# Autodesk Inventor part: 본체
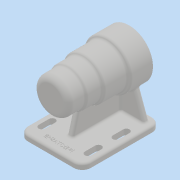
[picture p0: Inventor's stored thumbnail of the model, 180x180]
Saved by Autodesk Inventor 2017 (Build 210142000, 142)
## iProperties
Part Number: 본체
Material: 일반
Document SubType Name: Modeling
Designer: MRC
Density: 1 g/cm^3
Appearance: 기본값
Author: MRC
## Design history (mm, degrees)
sketch "스케치1"
  geometry: C1 r 34 at (0, 0); 1 further point
  constraints: 1 centre point, 1 coincident
  dimensions: "d0" = 68 diameter of C1
extrude "돌출1" new body sketch "스케치1" distance "d1" = 32; taper "d2" = 0 deg
sketch "스케치2"
  geometry: C1 r 34 at (0, 0) reference; C2 r 30 at (0, 0)
  constraints: 1 centre point, 1 coincident
  dimensions: "d3" = 60 diameter of C2
extrude "돌출2" join sketch "스케치2" distance "d4" = 34; taper "d5" = 0 deg
sketch "스케치3"
  geometry: C1 r 30 at (0, 0) reference; C2 r 27 at (0, 0)
  constraints: 1 centre point, 1 coincident
  dimensions: "d6" = 54 diameter of C2
extrude "돌출3" join sketch "스케치3" distance "d7" = 22; taper "d8" = 0 deg
sketch "스케치4"
  geometry: C1 r 27 at (0, 0) reference; C2 r 25 at (0, 0)
  constraints: 1 centre point, 1 coincident
  dimensions: "d9" = 50 diameter of C2
extrude "돌출4" join sketch "스케치4" distance "d10" = 24; taper "d11" = 0 deg
sketch "스케치5"
  geometry: L1 (0, 0)-(21, 0); L2 (21, 0)-(21, -15); L3 (21, -15)-(0, -15); L4 (0, -15)-(0, 0); L5 (0, -15)-(24, -15); L6 (24, -15)-(24, -69); L7 (24, -69)-(0, -69); L8 (0, -69)-(0, -15); L9 (0, -69)-(21, -69); L10 (21, -69)-(21, -81); L11 (21, -81)-(0, -81); L12 (0, -81)-(0, -69); L13 (0, -81)-(17.5, -81); L14 (17.5, -81)-(17.5, -99); L15 (17.5, -99)-(0, -99); L16 (0, -99)-(0, -81); L17 (0, -99)-(16, -99); L18 (16, -99)-(16, -103); L19 (16, -103)-(0, -103); L20 (0, -103)-(0, -99); L21 (0, -103)-(12.605, -103); L22 (-25, -112)-(25, -112) reference; L23 (0, -103)-(10.5, -103); L24 (10.5, -103)-(10.5, -106); L25 (10.5, -106)-(0, -106); L26 (0, -106)-(0, -103)
  constraints: 50 end point, 12 parallel, 7 horizontal, 6 perpendicular, 1 point on line
  dimensions: "d12" = 15 distance of L1.end L2.end; "d13" = 54 distance of L5.end L6.end; "d14" = 12 distance of L9.end L10.end; "d15" = 18 distance of L13.end L14.end; "d16" = 4 distance of L17.end L18.end; "d17" = 3 distance of L23.end L24.end; "d18" = 42 diameter of L2 L4; "d19" = 48 diameter of L6 L8; "d20" = 35 diameter of L14 L16; "d21" = 32 diameter of L18 L20; "d22" = 21 diameter of L24 L26
revolve "회전1" sketch "스케치5" stored, may be unused: angle "d23" = 90 deg
chamfer "모따기1" distance "d24" = 1; stored, may be unused: second distance "d25" = 2, angle "d26" = 45 deg
fillet "모깎기1" dims "d27" = 3
fillet "모깎기2" dims "d28" = 0.3
sketch "스케치6"
  geometry: C1 r 34 at (0, 0) reference; 1 further point
  constraints: 1 horizontal alignment
  dimensions: "d29" = 26 distance of C1.centre point (-26, 0)
hole "구멍1" sketch "스케치6" at (-26, 0) diameter "d30" = 3.242; stored, may be unused: countersink angle "d34" = 90 deg, drill point angle "d36" = 118 deg; dims "d31" = 8, "d32" = 4, "d33" = 2, "d35" = 11
node "작업 평면1"
sketch "스케치7"
  geometry: L1 (-45, -112)-(45, -112); L2 (45, -112)-(45, 0); L3 (45, 0)-(-45, 0); L4 (-45, 0)-(-45, -112); 2 further points
  constraints: 8 end point, 2 coincident, 2 parallel, 1 horizontal, 1 midpoint, 1 perpendicular
  dimensions: "d41" = 112 distance of L3.end L1.start; "d42" = 90 distance of L1.start L1.end
extrude "돌출5" join sketch "스케치7" distance "d43" = 8; taper "d44" = 0 deg
sketch "스케치8"
  geometry: L1 (33, 92)-(33, 77); L2 (28.5, 92)-(28.5, 77); L3 (37.5, 77)-(37.5, 92); L4 (33, 52)-(33, 37); L5 (28.5, 52)-(28.5, 37); L6 (37.5, 37)-(37.5, 52); L7 (45, 112)-(-45, 112) reference; A1 r 4.5 centre (33, 92) between (37.5, 92) and (28.5, 92); A2 r 4.5 centre (33, 77) between (28.5, 77) and (37.5, 77); A3 r 4.5 centre (33, 52) between (37.5, 52) and (28.5, 52); A4 r 4.5 centre (33, 37) between (28.5, 37) and (37.5, 37); 3 further points
  constraints: 16 end point, 8 point on circle, 8 tangent, 4 centre point, 2 midpoint, 2 parallel, 2 vertical, 1 vertical alignment
  dimensions: "d45" = 15 distance of L1.start L1.end; "d46" = 9 diameter of A2; "d48" = 33 horizontal distance of point (0, 0) point (33, 84.5); "d49" = 15 distance of L4.start L4.end; "d50" = 9 diameter of A4; "d51" = 25 distance of L4.start L1.end; "d87" = 20 distance from line of L1.start L7
extrude "돌출6" cut sketch "스케치8" stored distance "d52" = 8; taper "d53" = 0 deg
fillet "모깎기3" dims "d54" = 12
fillet "모깎기4" dims "d55" = 3
fillet "모깎기5" dims "d56" = 8
fillet "모깎기6" dims "d57" = 3
node "작업 평면2"
sketch "스케치11"
  geometry: L1 (4, 85)-(-4, 85); L2 (-4, 85)-(-4, 8); L3 (4, 8)-(4, 85); L4 (45, 12)-(45, 100) reference; L5 (-4, 8)-(4, 8); L6 (-33, 0)-(33, 0) reference; 4 further points
  constraints: 8 end point, 2 horizontal, 2 vertical alignment, 1 coincident, 1 midpoint, 1 parallel, 1 perpendicular
  dimensions: "d66" = 8 distance of L1.start L1.end; "d74" = 8 distance between parallel lines of L6 L5; "d75" = 77 distance from line of point (0, 8) L1
extrude "돌출7" join sketch "스케치11" stored distance "d68" = 8; taper "d69" = 0 deg
feature "면 기울기1" dims angle "d70" = 15 deg
node "작업 평면3"
sketch "스케치12"
  geometry: L1 (-31.663, -47.336)-(-37, -62); L2 (-42, -62)-(-33, -62) reference; L3 (-45, -65)-(-45, -70) reference; 1 further point
  constraints: 2 end point, 1 point on line
  dimensions: "d72" = 110 deg angle of L2 L1; "d73" = 8 distance from line of L3 L1.end
feature "리브1" sketch "스케치12" dims "d76" = 33, "d77" = 8, "d78" = 0, "d79" = 0, "d80" = 1, "d81" = 1
fillet "모깎기7" dims "d82" = 3
fillet "모깎기8" dims "d83" = 3
sketch "스케치13"
  geometry: L1 (-33, 109)-(33, 109) reference; L2 (33, 112)-(-33, 112) reference; 3 further points
  constraints: 1 midpoint, 1 vertical alignment, 1 other
  dimensions: "d84" = 12 distance from line of L2 point (0, 100)
feature "엠보싱1" sketch "스케치13" dims "d85" = 0.5, "d86" = 0
node "솔리드1"
pattern_circular "원형 패턴1" dims angle "d38" = 360 deg
mirror "미러1"
mirror "미러2"
other parameters: "d58" = -8, "d71" = -8
